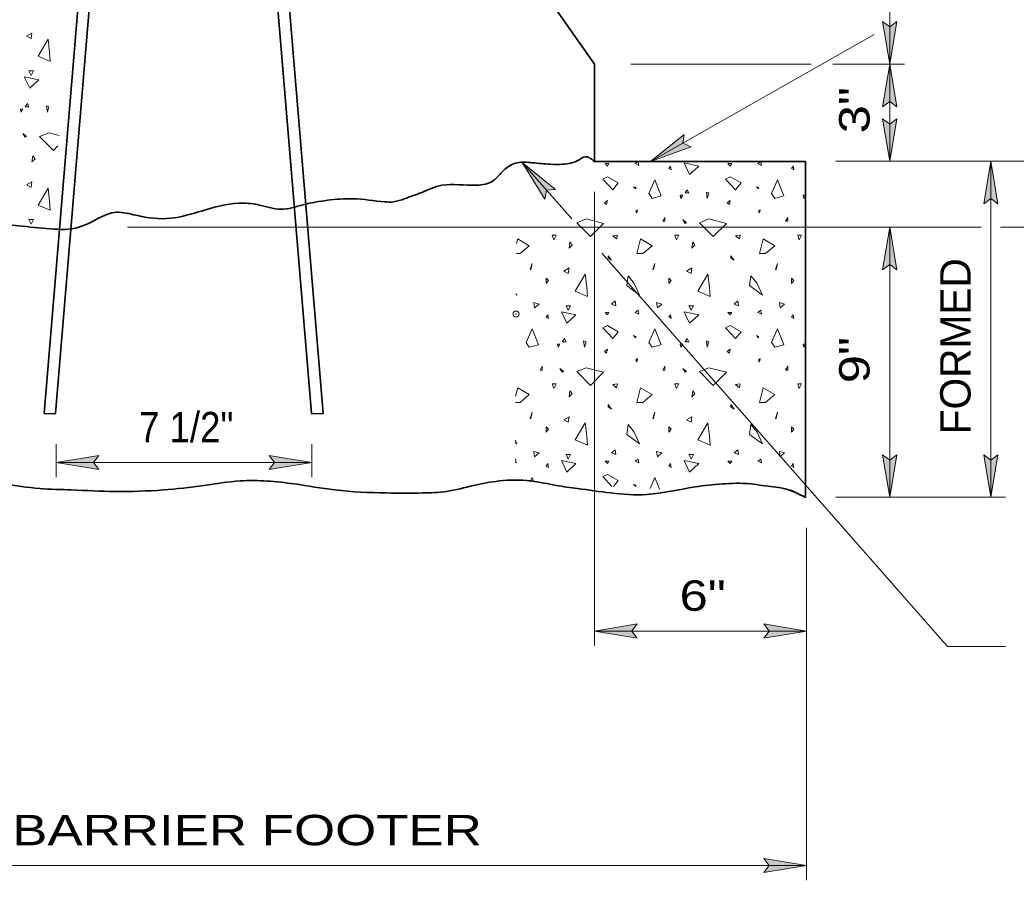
# Model space of a CAD drawing. Extents: x -9.07 to -2.08, y 8.04 to 17.77.
# Drawn here: x -6.332 to -4.365, y 13.001 to 14.699 of the extents above; entities that cross this region are included whole.
import ezdxf
from ezdxf.enums import TextEntityAlignment as Align

# ---------------------------------------------------------------- set-up
doc = ezdxf.new("R2010")
doc.units = 0
doc.header["$LTSCALE"] = 0.024
doc.header["$PDMODE"] = 32
doc.header["$PDSIZE"] = 0.012
for name, color, linetype, lineweight in [('1', 7, 'Continuous', 35), ('10', 7, 'Continuous', 13), ('12', 7, 'Continuous', 53), ('6', 7, 'Continuous', 13)]:
    doc.layers.add(name, color=color, linetype=linetype, lineweight=lineweight)

msp = doc.modelspace()

# ---------------------------------------------------------------- hatches: boundary and pattern name
at = {"layer": '10'}
for points in [[(-4.61433, 14.6115), (-4.60033, 14.69567), (-4.61433, 14.68517), (-4.62833, 14.69567)], [(-4.61433, 14.6115), (-4.60033, 14.5275), (-4.61433, 14.538), (-4.62833, 14.5275)], [(-4.61433, 14.49333), (-4.60033, 14.50383), (-4.61433, 14.41983), (-4.62833, 14.50383)], [(-5.08667, 14.4195), (-5.00667, 14.44867), (-5.02267, 14.45567), (-5.0205, 14.473)], [(-5.34033, 14.41767), (-5.27433, 14.36383), (-5.29183, 14.3625), (-5.29533, 14.34533)], [(-4.41483, 14.34633), (-4.40083, 14.33583), (-4.41483, 14.41983), (-4.42883, 14.33583)], [(-4.61433, 14.2895), (-4.60033, 14.2055), (-4.61433, 14.216), (-4.62833, 14.2055)], [(-6.18633, 13.825), (-6.17583, 13.811), (-6.25983, 13.825), (-6.17583, 13.839)], [(-5.75533, 13.825), (-5.83933, 13.811), (-5.82883, 13.825), (-5.83933, 13.839)], [(-4.61433, 13.7565), (-4.60033, 13.8405), (-4.61433, 13.83), (-4.62833, 13.8405)], [(-4.41483, 13.7565), (-4.40083, 13.8405), (-4.41483, 13.83), (-4.42883, 13.8405)], [(-5.11333, 13.50633), (-5.12383, 13.49233), (-5.11333, 13.47833), (-5.19733, 13.49233)], [(-4.77867, 13.49233), (-4.86267, 13.50633), (-4.85217, 13.49233), (-4.86267, 13.47833)], [(-4.77867, 13.0295), (-4.86267, 13.0435), (-4.85217, 13.0295), (-4.86267, 13.0155)]]:
    msp.add_hatch(color=256, dxfattribs=at).paths.add_polyline_path(points)

# ---------------------------------------------------------------- linework, layer by layer
at = {"layer": '1'}
for p, q in [((-6.284, 13.922), (-6.107, 16.04583)), ((-6.26133, 13.922), (-6.08433, 16.04483)), ((-5.93267, 16.04483), (-5.75567, 13.922)), ((-5.91, 16.04583), (-5.73283, 13.922)), ((-5.54633, 15.11033), (-5.19733, 14.6115)), ((-5.19733, 14.4195), (-5.19733, 14.6115)), ((-5.19733, 14.4195), (-4.78083, 14.4195)), ((-4.78083, 13.75633), (-4.78083, 14.4195)), ((-6.26133, 13.92117), (-6.284, 13.922)), ((-5.73283, 13.922), (-5.75567, 13.92117))]:
    msp.add_line(p, q, dxfattribs=at)
at = {"layer": '10'}
for p, q in [((-5.08667, 14.4195), (-4.64483, 14.67)), ((-5.12533, 14.6115), (-4.7695, 14.6115)), ((-4.72667, 14.6115), (-4.5855, 14.6115)), ((-4.62833, 14.50383), (-4.61433, 14.41983)), ((-4.62833, 14.50383), (-4.61433, 14.49333)), ((-4.60033, 14.50383), (-4.61433, 14.41983)), ((-4.60033, 14.50383), (-4.61433, 14.49333)), ((-5.0205, 14.473), (-5.08667, 14.4195)), ((-5.0205, 14.473), (-5.02267, 14.45567)), ((-5.00667, 14.44867), (-5.02267, 14.45567)), ((-5.00667, 14.44867), (-5.08667, 14.4195)), ((-5.29533, 14.34533), (-5.34033, 14.41767)), ((-5.27433, 14.36383), (-5.34033, 14.41767)), ((-5.24233, 14.30617), (-5.34033, 14.41767)), ((-4.72083, 14.41983), (-4.18633, 14.41983)), ((-4.42883, 14.33583), (-4.41483, 14.41983)), ((-4.40083, 14.33583), (-4.41483, 14.41983)), ((-4.41483, 14.41983), (-4.41483, 13.7565)), ((-5.29533, 14.34533), (-5.29183, 14.3625)), ((-5.27433, 14.36383), (-5.29183, 14.3625)), ((-5.19733, 14.3595), (-5.19733, 13.46367)), ((-4.42883, 14.33583), (-4.41483, 14.34633)), ((-4.40083, 14.33583), (-4.41483, 14.34633)), ((-6.11933, 14.2895), (-4.434, 14.2895)), ((-4.62833, 14.2055), (-4.61433, 14.2895)), ((-4.60033, 14.2055), (-4.61433, 14.2895)), ((-4.61433, 14.2895), (-4.61433, 13.7565)), ((-4.3955, 14.2895), (-4.18633, 14.2895)), ((-4.5, 13.46217), (-5.183, 14.23867)), ((-4.62833, 14.2055), (-4.61433, 14.216)), ((-4.60033, 14.2055), (-4.61433, 14.216)), ((-6.25983, 13.86117), (-6.25983, 13.79617)), ((-5.75533, 13.86117), (-5.75533, 13.79617)), ((-6.17583, 13.839), (-6.25983, 13.825)), ((-6.17583, 13.839), (-6.18633, 13.825)), ((-5.83933, 13.839), (-5.75533, 13.825)), ((-5.83933, 13.839), (-5.82883, 13.825)), ((-4.62833, 13.8405), (-4.61433, 13.7565)), ((-4.62833, 13.8405), (-4.61433, 13.83)), ((-4.60033, 13.8405), (-4.61433, 13.7565)), ((-4.60033, 13.8405), (-4.61433, 13.83)), ((-4.42883, 13.8405), (-4.41483, 13.7565)), ((-4.42883, 13.8405), (-4.41483, 13.83)), ((-4.40083, 13.8405), (-4.41483, 13.7565)), ((-4.40083, 13.8405), (-4.41483, 13.83)), ((-6.17583, 13.811), (-6.25983, 13.825)), ((-6.25983, 13.825), (-5.75533, 13.825)), ((-6.17583, 13.811), (-6.18633, 13.825)), ((-5.83933, 13.811), (-5.75533, 13.825)), ((-5.83933, 13.811), (-5.82883, 13.825)), ((-4.72083, 13.7565), (-4.386, 13.7565)), ((-4.77867, 13.69633), (-4.77867, 13.00067)), ((-5.19733, 13.49233), (-4.77867, 13.49233)), ((-4.38567, 13.46217), (-4.5, 13.46217)), ((-7.227, 13.0295), (-4.77867, 13.0295))]:
    msp.add_line(p, q, dxfattribs=at)
msp.add_lwpolyline([(-4.61433, 14.41983), (-4.61433, 14.6115), (-4.61433, 15.26)], dxfattribs=at)
for points in [[(-4.61433, 14.6115), (-4.60033, 14.69567), (-4.61433, 14.68517), (-4.62833, 14.69567)], [(-4.61433, 14.6115), (-4.60033, 14.5275), (-4.61433, 14.538), (-4.62833, 14.5275)], [(-4.61433, 14.49333), (-4.60033, 14.50383), (-4.61433, 14.41983), (-4.62833, 14.50383)], [(-5.08667, 14.4195), (-5.00667, 14.44867), (-5.02267, 14.45567), (-5.0205, 14.473)], [(-5.34033, 14.41767), (-5.27433, 14.36383), (-5.29183, 14.3625), (-5.29533, 14.34533)], [(-4.41483, 14.34633), (-4.40083, 14.33583), (-4.41483, 14.41983), (-4.42883, 14.33583)], [(-4.61433, 14.2895), (-4.60033, 14.2055), (-4.61433, 14.216), (-4.62833, 14.2055)], [(-6.18633, 13.825), (-6.17583, 13.811), (-6.25983, 13.825), (-6.17583, 13.839)], [(-5.75533, 13.825), (-5.83933, 13.811), (-5.82883, 13.825), (-5.83933, 13.839)], [(-4.61433, 13.7565), (-4.60033, 13.8405), (-4.61433, 13.83), (-4.62833, 13.8405)], [(-4.41483, 13.7565), (-4.40083, 13.8405), (-4.41483, 13.83), (-4.42883, 13.8405)], [(-5.11333, 13.50633), (-5.12383, 13.49233), (-5.11333, 13.47833), (-5.19733, 13.49233)], [(-4.77867, 13.49233), (-4.86267, 13.50633), (-4.85217, 13.49233), (-4.86267, 13.47833)], [(-4.77867, 13.0295), (-4.86267, 13.0435), (-4.85217, 13.0295), (-4.86267, 13.0155)]]:
    msp.add_lwpolyline(points, close=True, dxfattribs=at)
at = {"layer": '10', "lineweight": 35}
for points in [[(-6.81067, 14.29567), (-6.74767, 14.2955), (-6.715, 14.30133), (-6.6585, 14.30133), (-6.62867, 14.2955), (-6.599, 14.2925), (-6.55133, 14.2895), (-6.51267, 14.2925), (-6.46517, 14.29833), (-6.4205, 14.30133), (-6.38483, 14.29833), (-6.33433, 14.2925), (-6.27183, 14.2865), (-6.21533, 14.2895), (-6.141, 14.31917), (-6.10233, 14.31317), (-6.03383, 14.30733), (-5.9715, 14.32217), (-5.9, 14.337), (-5.86133, 14.334), (-5.81683, 14.325), (-5.77217, 14.334), (-5.7245, 14.34283), (-5.674, 14.34583), (-5.6115, 14.33983), (-5.59367, 14.33983), (-5.57283, 14.34583), (-5.54017, 14.35767), (-5.4985, 14.3725), (-5.43017, 14.3725), (-5.39733, 14.38133), (-5.3765, 14.40217), (-5.34983, 14.417), (-5.32, 14.417), (-5.28433, 14.414), (-5.26067, 14.414), (-5.22783, 14.42283), (-5.216, 14.42883), (-5.19733, 14.4195)], [(-7.227, 13.773), (-7.173, 13.768), (-7.10767, 13.77383), (-7.057, 13.77683), (-7.0095, 13.771), (-6.97083, 13.771), (-6.947, 13.771), (-6.8875, 13.77383), (-6.86067, 13.77683), (-6.819, 13.77983), (-6.7745, 13.77683), (-6.72683, 13.77383), (-6.68233, 13.771), (-6.64367, 13.77683), (-6.56917, 13.77683), (-6.49783, 13.78283), (-6.4205, 13.78867), (-6.364, 13.78283), (-6.29267, 13.77383), (-6.23017, 13.771), (-6.144, 13.768), (-6.04883, 13.771), (-5.9685, 13.77983), (-5.897, 13.78867), (-5.79, 13.78283), (-5.70967, 13.771), (-5.6085, 13.765), (-5.53717, 13.765), (-5.4895, 13.768), (-5.436, 13.77983), (-5.3855, 13.78867), (-5.323, 13.78867), (-5.2725, 13.77983), (-5.23083, 13.77383), (-5.16533, 13.765), (-5.094, 13.762), (-4.99883, 13.77683), (-4.94533, 13.78283), (-4.88883, 13.78283), (-4.84417, 13.77683), (-4.82333, 13.77383), (-4.78083, 13.75633), (-4.8115, 13.771)]]:
    msp.add_spline(points, degree=3, dxfattribs=at)
at = {"layer": '6'}
for points in [[(-6.3185, 14.667), (-6.3095, 14.66233), (-6.308, 14.673)], [(-6.27317, 14.63483), (-6.27167, 14.61683), (-6.29583, 14.62733), (-6.276, 14.66083)], [(-6.31383, 14.5985), (-6.3095, 14.5895), (-6.30483, 14.5985)], [(-6.32317, 14.58667), (-6.31233, 14.564), (-6.29433, 14.5805)], [(-6.33067, 14.523), (-6.32933, 14.51683), (-6.326, 14.523)], [(-6.317, 14.53367), (-6.31383, 14.52767), (-6.32133, 14.52767)], [(-6.27917, 14.529), (-6.2775, 14.51683), (-6.2745, 14.52767)], [(-6.32133, 14.46717), (-6.3185, 14.4685), (-6.326, 14.47467)], [(-6.30617, 14.43083), (-6.308, 14.4185), (-6.30183, 14.42467)], [(-5.02033, 14.41667), (-5.0095, 14.39383), (-4.9915, 14.4105)], [(-5.17617, 14.41517), (-5.1715, 14.4105), (-5.16867, 14.41517)], [(-5.0505, 14.40583), (-5.04583, 14.40283), (-5.04733, 14.4105)], [(-4.93383, 14.41517), (-4.92917, 14.4105), (-4.92633, 14.41517)], [(-4.80817, 14.40583), (-4.8035, 14.40283), (-4.805, 14.4105)], [(-6.3185, 14.37317), (-6.3095, 14.3685), (-6.308, 14.37933)], [(-5.18083, 14.38483), (-5.16117, 14.36367), (-5.15033, 14.377), (-5.1715, 14.38917)], [(-5.08367, 14.34667), (-5.06567, 14.3515), (-5.07783, 14.38317), (-5.08983, 14.35617)], [(-4.9385, 14.38483), (-4.91883, 14.36367), (-4.908, 14.377), (-4.92917, 14.38917)], [(-4.84133, 14.34667), (-4.82333, 14.3515), (-4.83567, 14.38317), (-4.8475, 14.35617)], [(-6.27317, 14.34117), (-6.27167, 14.32317), (-6.29583, 14.3335), (-6.276, 14.367)], [(-5.11567, 14.368), (-5.12, 14.3695), (-5.11567, 14.36517)], [(-5.01417, 14.36367), (-5.011, 14.3575), (-5.0185, 14.3575)], [(-4.97633, 14.359), (-4.9745, 14.34667), (-4.97167, 14.3575)], [(-4.87333, 14.368), (-4.87767, 14.3695), (-4.87333, 14.36517)], [(-5.17767, 14.33767), (-5.17333, 14.33483), (-5.1715, 14.3425)], [(-5.02783, 14.35283), (-5.0265, 14.34667), (-5.02317, 14.35283)], [(-4.93533, 14.33767), (-4.931, 14.33483), (-4.92917, 14.3425)], [(-4.7855, 14.35283), (-4.78417, 14.34667), (-4.78083, 14.35283)], [(-5.1125, 14.324), (-5.11567, 14.32117), (-5.114, 14.318)], [(-4.87017, 14.324), (-4.87333, 14.32117), (-4.87167, 14.318)], [(-6.31383, 14.30467), (-6.3095, 14.29567), (-6.30483, 14.30467)], [(-5.214, 14.306), (-5.17917, 14.297), (-5.205, 14.27117), (-5.23233, 14.2985)], [(-5.05817, 14.309), (-5.0625, 14.30133), (-5.05817, 14.30133)], [(-5.0185, 14.297), (-5.01567, 14.2985), (-5.02317, 14.30467)], [(-4.97167, 14.306), (-4.93683, 14.297), (-4.96267, 14.27117), (-4.99, 14.2985)], [(-4.81583, 14.309), (-4.82017, 14.30133), (-4.81583, 14.30133)], [(-5.28067, 14.274), (-5.27767, 14.265), (-5.273, 14.274)], [(-5.24567, 14.26067), (-5.2475, 14.2485), (-5.24133, 14.2545)], [(-5.16117, 14.2725), (-5.1535, 14.2665), (-5.15217, 14.274)], [(-5.102, 14.23767), (-5.08367, 14.25317), (-5.10633, 14.2665), (-5.114, 14.23767)], [(-5.03833, 14.274), (-5.0355, 14.265), (-5.03067, 14.274)], [(-5.00333, 14.26067), (-5.00517, 14.2485), (-4.999, 14.2545)], [(-4.91883, 14.2725), (-4.91117, 14.2665), (-4.90983, 14.274)], [(-4.85967, 14.23767), (-4.84133, 14.25317), (-4.864, 14.2665), (-4.87167, 14.23767)], [(-4.796, 14.274), (-4.79317, 14.265), (-4.7885, 14.274)], [(-5.17017, 14.23333), (-5.17017, 14.22867), (-5.164, 14.22433)], [(-4.92783, 14.23333), (-4.92783, 14.22867), (-4.92167, 14.22433)], [(-5.3245, 14.206), (-5.32317, 14.206), (-5.32017, 14.21817)], [(-5.258, 14.203), (-5.249, 14.19833), (-5.2475, 14.20917)], [(-5.08217, 14.206), (-5.08083, 14.206), (-5.07783, 14.21817)], [(-5.01567, 14.203), (-5.00667, 14.19833), (-5.00517, 14.20917)], [(-4.84, 14.206), (-4.8385, 14.206), (-4.83567, 14.21817)], [(-5.29283, 14.18933), (-5.29283, 14.17867), (-5.28817, 14.18467)], [(-5.2125, 14.171), (-5.21117, 14.153), (-5.23533, 14.1635), (-5.2155, 14.197)], [(-5.13083, 14.19367), (-5.13367, 14.17433), (-5.10817, 14.15583), (-5.11867, 14.17867)], [(-5.0505, 14.18933), (-5.0505, 14.17867), (-5.04583, 14.18467)], [(-4.97033, 14.171), (-4.96883, 14.153), (-4.993, 14.1635), (-4.97317, 14.197)], [(-4.8885, 14.19367), (-4.89133, 14.17433), (-4.86583, 14.15583), (-4.87633, 14.17867)], [(-4.80817, 14.18933), (-4.80817, 14.17867), (-4.8035, 14.18467)], [(-5.15633, 14.144), (-5.164, 14.13783), (-5.155, 14.13467)], [(-4.91417, 14.144), (-4.92167, 14.13783), (-4.91267, 14.13467)], [(-5.317, 14.14083), (-5.3155, 14.13033), (-5.3065, 14.13783)], [(-5.26267, 14.12283), (-5.25183, 14.10017), (-5.23383, 14.11667)], [(-5.25333, 14.13467), (-5.249, 14.12567), (-5.24433, 14.13467)], [(-5.17617, 14.12133), (-5.1715, 14.11667), (-5.16867, 14.12133)], [(-5.11717, 14.12133), (-5.10967, 14.11817), (-5.111, 14.12567)], [(-5.07467, 14.14083), (-5.07317, 14.13033), (-5.06417, 14.13783)], [(-5.02033, 14.12283), (-5.0095, 14.10017), (-4.9915, 14.11667)], [(-5.011, 14.13467), (-5.00667, 14.12567), (-5.002, 14.13467)], [(-4.93383, 14.12133), (-4.92917, 14.11667), (-4.92633, 14.12133)], [(-4.87483, 14.12133), (-4.86733, 14.11817), (-4.86867, 14.12567)], [(-4.83233, 14.14083), (-4.83083, 14.13033), (-4.82183, 14.13783)], [(-5.29283, 14.112), (-5.28817, 14.10917), (-5.28967, 14.11667)], [(-5.0505, 14.112), (-5.04583, 14.10917), (-5.04733, 14.11667)], [(-4.80817, 14.112), (-4.8035, 14.10917), (-4.805, 14.11667)], [(-5.326, 14.053), (-5.308, 14.05767), (-5.32017, 14.08933), (-5.33217, 14.06233)], [(-5.18083, 14.09117), (-5.16117, 14.06983), (-5.15033, 14.08317), (-5.1715, 14.0955)], [(-5.08367, 14.053), (-5.06567, 14.05767), (-5.07783, 14.08933), (-5.08983, 14.06233)], [(-4.9385, 14.09117), (-4.91883, 14.06983), (-4.908, 14.08317), (-4.92917, 14.0955)], [(-4.84133, 14.053), (-4.82333, 14.05767), (-4.83567, 14.08933), (-4.8475, 14.06233)], [(-5.2565, 14.06983), (-5.25333, 14.06367), (-5.26083, 14.06367)], [(-5.21867, 14.06517), (-5.21683, 14.053), (-5.214, 14.06367)], [(-5.11567, 14.07417), (-5.12, 14.07567), (-5.11567, 14.07133)], [(-5.01417, 14.06983), (-5.011, 14.06367), (-5.0185, 14.06367)], [(-4.97633, 14.06517), (-4.9745, 14.053), (-4.97167, 14.06367)], [(-4.87333, 14.07417), (-4.87767, 14.07567), (-4.87333, 14.07133)], [(-5.27017, 14.059), (-5.26867, 14.053), (-5.2655, 14.059)], [(-5.17767, 14.044), (-5.17333, 14.041), (-5.1715, 14.04867)], [(-5.02783, 14.059), (-5.0265, 14.053), (-5.02317, 14.059)], [(-4.93533, 14.044), (-4.931, 14.041), (-4.92917, 14.04867)], [(-4.7855, 14.059), (-4.78417, 14.053), (-4.78083, 14.059)], [(-5.1125, 14.03017), (-5.11567, 14.02733), (-5.114, 14.02417)], [(-4.87017, 14.03017), (-4.87333, 14.02733), (-4.87167, 14.02417)], [(-5.3005, 14.01517), (-5.30483, 14.0075), (-5.3005, 14.0075)], [(-5.26083, 14.00317), (-5.258, 14.00467), (-5.2655, 14.01083)], [(-5.214, 14.01217), (-5.17917, 14.00317), (-5.205, 13.97733), (-5.23233, 14.00467)], [(-5.05817, 14.01517), (-5.0625, 14.0075), (-5.05817, 14.0075)], [(-5.0185, 14.00317), (-5.01567, 14.00467), (-5.02317, 14.01083)], [(-4.97167, 14.01217), (-4.93683, 14.00317), (-4.96267, 13.97733), (-4.99, 14.00467)], [(-4.81583, 14.01517), (-4.82017, 14.0075), (-4.81583, 14.0075)], [(-5.28067, 13.98017), (-5.27767, 13.97117), (-5.273, 13.98017)], [(-5.24567, 13.96683), (-5.2475, 13.95467), (-5.24133, 13.96083)], [(-5.16117, 13.97883), (-5.1535, 13.97267), (-5.15217, 13.98017)], [(-5.102, 13.94383), (-5.08367, 13.95933), (-5.10633, 13.97267), (-5.114, 13.94383)], [(-5.03833, 13.98017), (-5.0355, 13.97117), (-5.03067, 13.98017)], [(-5.00333, 13.96683), (-5.00517, 13.95467), (-4.999, 13.96083)], [(-4.91883, 13.97883), (-4.91117, 13.97267), (-4.90983, 13.98017)], [(-4.85967, 13.94383), (-4.84133, 13.95933), (-4.864, 13.97267), (-4.87167, 13.94383)], [(-4.796, 13.98017), (-4.79317, 13.97117), (-4.7885, 13.98017)], [(-5.17017, 13.9395), (-5.17017, 13.93483), (-5.164, 13.9305)], [(-4.92783, 13.9395), (-4.92783, 13.93483), (-4.92167, 13.9305)], [(-5.3245, 13.91217), (-5.32317, 13.91217), (-5.32017, 13.92433)], [(-5.258, 13.90933), (-5.249, 13.90467), (-5.2475, 13.91533)], [(-5.08217, 13.91217), (-5.08083, 13.91217), (-5.07783, 13.92433)], [(-5.01567, 13.90933), (-5.00667, 13.90467), (-5.00517, 13.91533)], [(-4.84, 13.91217), (-4.8385, 13.91217), (-4.83567, 13.92433)], [(-5.29283, 13.89567), (-5.29283, 13.88483), (-5.28817, 13.89083)], [(-5.2125, 13.87717), (-5.21117, 13.85917), (-5.23533, 13.86967), (-5.2155, 13.90317)], [(-5.13083, 13.89983), (-5.13367, 13.8805), (-5.10817, 13.86217), (-5.11867, 13.88483)], [(-5.0505, 13.89567), (-5.0505, 13.88483), (-5.04583, 13.89083)], [(-4.97033, 13.87717), (-4.96883, 13.85917), (-4.993, 13.86967), (-4.97317, 13.90317)], [(-4.8885, 13.89983), (-4.89133, 13.8805), (-4.86583, 13.86217), (-4.87633, 13.88483)], [(-4.80817, 13.89567), (-4.80817, 13.88483), (-4.8035, 13.89083)], [(-5.317, 13.847), (-5.3155, 13.8365), (-5.3065, 13.84417)], [(-5.15633, 13.85017), (-5.164, 13.84417), (-5.155, 13.84083)], [(-5.07467, 13.847), (-5.07317, 13.8365), (-5.06417, 13.84417)], [(-4.91417, 13.85017), (-4.92167, 13.84417), (-4.91267, 13.84083)], [(-4.83233, 13.847), (-4.83083, 13.8365), (-4.82183, 13.84417)], [(-5.26267, 13.829), (-5.25183, 13.80633), (-5.23383, 13.82283)], [(-5.25333, 13.84083), (-5.249, 13.83183), (-5.24433, 13.84083)], [(-5.17617, 13.8275), (-5.1715, 13.82283), (-5.16867, 13.8275)], [(-5.11717, 13.8275), (-5.10967, 13.82433), (-5.111, 13.83183)], [(-5.02033, 13.829), (-5.0095, 13.80633), (-4.9915, 13.82283)], [(-5.011, 13.84083), (-5.00667, 13.83183), (-5.002, 13.84083)], [(-4.93383, 13.8275), (-4.92917, 13.82283), (-4.92633, 13.8275)], [(-4.87483, 13.8275), (-4.86733, 13.82433), (-4.86867, 13.83183)], [(-5.29283, 13.81817), (-5.28817, 13.81533), (-5.28967, 13.82283)], [(-5.0505, 13.81817), (-5.04583, 13.81533), (-5.04733, 13.82283)], [(-4.80817, 13.81817), (-4.8035, 13.81533), (-4.805, 13.82283)], [(-5.11567, 13.78033), (-5.12, 13.78183), (-5.11567, 13.7775)]]:
    msp.add_lwpolyline(points, close=True, dxfattribs=at)
for points in [[(-6.2565, 14.45017), (-6.2655, 14.44117), (-6.29283, 14.4685), (-6.2745, 14.47617), (-6.2545, 14.471)], [(-5.11317, 14.418), (-5.11717, 14.41517), (-5.10967, 14.41183), (-5.11083, 14.418)], [(-4.86933, 14.419), (-4.87483, 14.41517), (-4.86733, 14.41183), (-4.86867, 14.419)], [(-5.351, 14.23767), (-5.34433, 14.23767), (-5.326, 14.25317), (-5.34867, 14.2665), (-5.351, 14.25783)], [(-5.35167, 14.15667), (-5.3505, 14.15583), (-5.35167, 14.1585)], [(-5.35317, 13.94383), (-5.34433, 13.94383), (-5.326, 13.95933), (-5.34867, 13.97267), (-5.353, 13.95583)], [(-5.35383, 13.8645), (-5.3505, 13.86217), (-5.35367, 13.86917)], [(-5.354, 13.82517), (-5.352, 13.82433), (-5.35333, 13.83183), (-5.354, 13.8315)], [(-5.31683, 13.78667), (-5.32017, 13.7955), (-5.324, 13.787)], [(-5.15967, 13.77767), (-5.15033, 13.78933), (-5.1715, 13.80167), (-5.18083, 13.79733), (-5.16283, 13.778)], [(-5.069, 13.77267), (-5.07783, 13.7955), (-5.0875, 13.77367)]]:
    msp.add_lwpolyline(points, dxfattribs=at)
msp.add_point((-5.352, 14.11817), dxfattribs=at)

# ---------------------------------------------------------------- texts
at = {"layer": '12', "width": 1.25}
for s, p in [('3"', (-4.65425, 14.52075)), ('9"', (-4.65425, 14.02725))]:
    msp.add_text(s, height=0.06001, rotation=90, dxfattribs=at).set_placement(p, align=Align.CENTER)
at = {"layer": '12'}
msp.add_text('FORMED', height=0.06001, rotation=90, dxfattribs=at).set_placement((-4.45475, 14.05462), align=Align.CENTER)
for s, width, p in [('7 1/2"', 0.9, (-6.00329, 13.865)), ('6"', 1.25, (-4.98367, 13.53233)), ('3\'-0" BARRIER FOOTER', 1.3, (-6.00162, 13.06942))]:
    msp.add_text(s, height=0.06001, dxfattribs=dict(at, width=width)).set_placement(p, align=Align.CENTER)

doc.saveas('drawing.dxf')
